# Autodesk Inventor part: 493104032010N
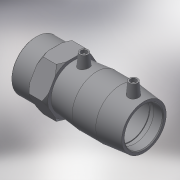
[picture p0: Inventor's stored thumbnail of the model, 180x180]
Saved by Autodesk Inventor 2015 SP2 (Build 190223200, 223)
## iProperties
Created: 2017-06
Part Number: 493104032010N
Material: Generic
Description: PLASSON FEMALE TRANSITION COUPLER 32 x 1"
Document SubType Name: Modeling
Designer: KIM
Mass: 108.676 g
Surface Area: 353.796 cm^2
Volume: 108.676 cm^3
Density: 1 g/cm^3
Appearance: Default
Author: KIM
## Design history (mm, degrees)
derived "493104.ipt"
feature "Solid1::493104.ipt"
tag "TaggingFeature1"
body "Solid1"
other parameters: "d1" = 32, "d2" = 44, "d3" = 44, "d5" = 39.6, "d6" = 30.4, "d7" = 32, "d8" = 168 deg, "d10" = 17.6, "d11" = 5.86667, "d29" = 43, "d30" = 14, "d31" = 31.5, "d34" = 5 deg, "d41" = 4, "d42" = 14, "d43" = 0, "d48" = 3, "d49" = 0, "d57" = 27, "d59" = 30.291, "d60" = 36, "d70" = 44, "d72" = 0, "d73" = 45 deg, "d74" = 2.7, "d75" = 45 deg, "d77" = 0.48, "d80" = 0.64, "d_" = 32, "L_1" = 44, "D_1" = 44, "A_" = 43, "d_2" = 12, "D_" = 27, "R_p" = 30.291
